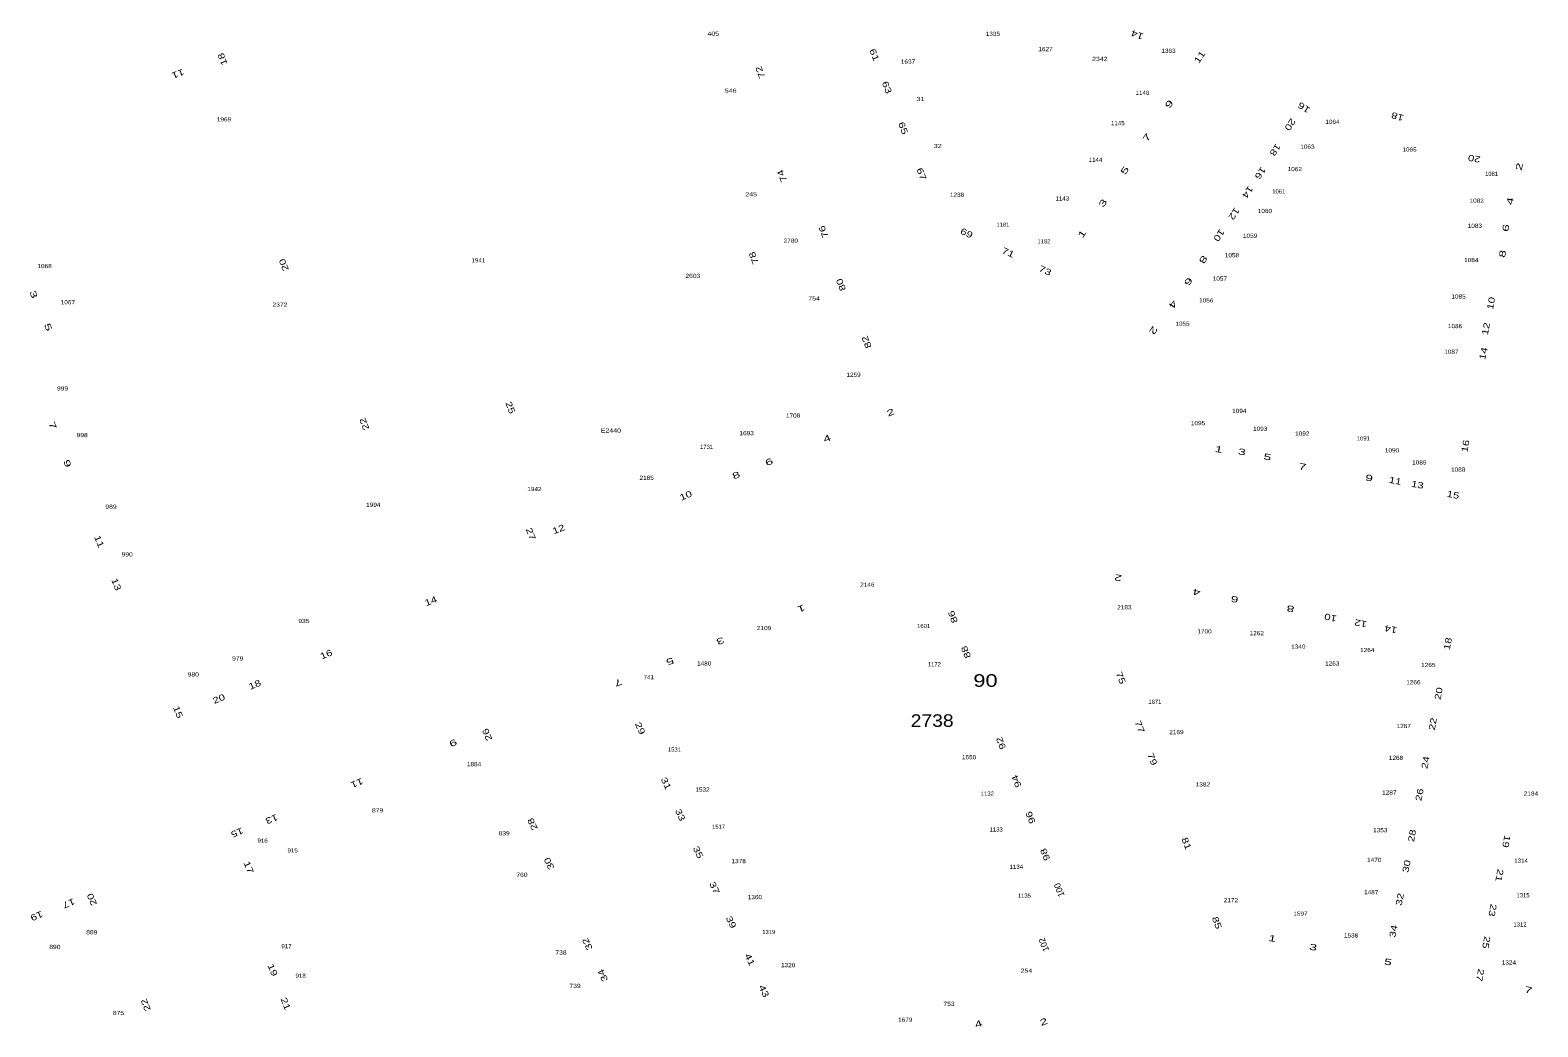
# Model space of a CAD drawing. Extents: x -828673 to -815583, y -1077737 to -1063807.
# Drawn here: x -821834.7 to -821473.8, y -1071578.1 to -1071339.7 of the extents above; entities that cross this region are included whole.
import ezdxf
from ezdxf.enums import TextEntityAlignment as Align

# ---------------------------------------------------------------- set-up
doc = ezdxf.new("R2010")
doc.units = 0
doc.header["$LTSCALE"] = 0.4
doc.layers.add('1', color=7, linetype='Continuous')
doc.layers.add('2', color=7, linetype='Continuous')

msp = doc.modelspace()

# ---------------------------------------------------------------- texts
at = {"layer": '1'}
for s, height, width, p in [('405', 1, 1.25, (-821671.188, -1071341.038)), ('1335', 1, 1.15, (-821604.281, -1071341.054)), ('1627', 1, 1.15, (-821591.685, -1071344.708)), ('1363', 1, 1.15, (-821562.25, -1071345.113)), ('1637', 1, 1.15, (-821624.588, -1071347.691)), ('2342', 1, 1.25, (-821578.668, -1071347.05)), ('546', 1, 1.25, (-821667.027, -1071354.653)), ('31', 1, 1.3, (-821621.598, -1071356.638)), ('1146', 1, 1.1, (-821568.474, -1071355.165)), ('1969', 1, 1.15, (-821788.3, -1071361.508)), ('1145', 1, 1.1, (-821574.374, -1071362.426)), ('1064', 1, 1.15, (-821522.997, -1071362.098)), ('32', 1, 1.3, (-821617.463, -1071367.889)), ('1144', 1, 1.1, (-821579.713, -1071371.186)), ('1063', 1, 1.15, (-821528.998, -1071368.038)), ('1065', 1, 1.15, (-821504.567, -1071368.736)), ('1062', 1, 1.15, (-821532.014, -1071373.407)), ('1081', 1, 1.05, (-821484.914, -1071374.549)), ('245', 1, 1.25, (-821662.136, -1071379.447)), ('1238', 1, 1.15, (-821612.847, -1071379.547)), ('1143', 1, 1.1, (-821587.656, -1071380.437)), ('1061', 1, 1.05, (-821535.851, -1071378.752)), ('1082', 1, 1.15, (-821488.47, -1071380.966)), ('1060', 1, 1.15, (-821539.184, -1071383.421)), ('1083', 1, 1.15, (-821488.92, -1071386.975)), ('2780', 1, 1.15, (-821652.642, -1071390.526)), ('1182', 1, 1.05, (-821592.057, -1071390.696)), ('1059', 1, 1.15, (-821542.709, -1071389.362)), ('1941', 1, 1.1, (-821727.402, -1071395.23)), ('1058', 1, 1.15, (-821547.052, -1071394.011)), ('1084', 1, 1.15, (-821489.778, -1071395.171)), ('1068', 1, 1.15, (-821831.238, -1071396.601)), ('2603', 1, 1.2, (-821676.094, -1071398.954)), ('1057', 1, 1.15, (-821549.942, -1071399.602)), ('1067', 1, 1.15, (-821825.68, -1071405.256)), ('2372', 1, 1.2, (-821774.924, -1071405.843)), ('754', 1, 1.25, (-821647.065, -1071404.341)), ('1056', 1, 1.15, (-821553.212, -1071404.811)), ('1085', 1, 1.15, (-821492.82, -1071403.88)), ('1055', 1, 1.15, (-821558.892, -1071410.391)), ('1086', 1, 1.15, (-821493.646, -1071410.964)), ('1087', 1, 1.15, (-821494.535, -1071417.095)), ('1259', 1, 1.15, (-821637.617, -1071422.609)), ('999', 1, 1.2, (-821826.937, -1071425.871)), ('1708', 1, 1.15, (-821652.095, -1071432.365)), ('1094', 1, 1.15, (-821545.293, -1071431.249)), ('E2440', 1, 1.25, (-821695.687, -1071435.934)), ('1095', 1, 1.15, (-821555.174, -1071434.17)), ('1093', 1, 1.15, (-821540.287, -1071435.527)), ('998', 1, 1.2, (-821822.249, -1071437.041)), ('1693', 1, 1.15, (-821663.208, -1071436.577)), ('1092', 1, 1.15, (-821530.223, -1071436.674)), ('1091', 1, 1.05, (-821515.61, -1071437.832)), ('1731', 1, 1.05, (-821672.802, -1071439.858)), ('1090', 1, 1.15, (-821508.752, -1071440.69)), ('1089', 1, 1.15, (-821502.211, -1071443.581)), ('1088', 1, 1.15, (-821492.909, -1071445.296)), ('1942', 1, 1.15, (-821714.001, -1071449.947)), ('2185', 1, 1.15, (-821687.145, -1071447.254)), ('989', 1, 1.2, (-821815.346, -1071454.17)), ('1994', 1, 1.15, (-821752.564, -1071453.718)), ('990', 1, 1.2, (-821811.48, -1071465.581)), ('2146', 1, 1.15, (-821634.337, -1071472.817)), ('2183', 1, 1.15, (-821572.807, -1071478.229)), ('935', 1, 1.2, (-821769.168, -1071481.521)), ('1601', 1, 1.05, (-821620.839, -1071482.708)), ('2109', 1, 1.15, (-821659.034, -1071483.204)), ('1700', 1, 1.15, (-821553.616, -1071483.989)), ('1262', 1, 1.15, (-821541.116, -1071484.413)), ('1340', 1, 1.15, (-821531.174, -1071487.639)), ('1264', 1, 1.15, (-821514.664, -1071488.45)), ('979', 1, 1.2, (-821785.02, -1071490.467)), ('1480', 1, 1.15, (-821673.374, -1071491.669)), ('1172', 1, 1.05, (-821618.276, -1071491.857)), ('1263', 1, 1.15, (-821523.051, -1071491.683)), ('1265', 1, 1.15, (-821500.052, -1071492.027)), ('980', 1, 1.2, (-821795.652, -1071494.286)), ('741', 1, 1.1, (-821686.628, -1071494.94)), ('1266', 1, 1.15, (-821503.633, -1071496.163)), ('1671', 1, 1.05, (-821565.501, -1071500.845)), ('2738', 3, 1.15, (-821618.809, -1071506.34)), ('2169', 1, 1.15, (-821560.335, -1071508.091)), ('1267', 1, 1.15, (-821505.926, -1071506.622)), ('1531', 1, 1.05, (-821680.487, -1071512.267)), ('1650', 1, 1.15, (-821609.978, -1071514.095)), ('1268', 1, 1.15, (-821507.791, -1071514.243)), ('1884', 1, 1.15, (-821728.459, -1071515.769)), ('1532', 1, 1.15, (-821673.773, -1071521.832)), ('1382', 1, 1.15, (-821554.004, -1071520.599)), ('1287', 1, 1.15, (-821509.381, -1071522.534)), ('1132', 1, 1.05, (-821605.604, -1071522.803)), ('2184', 1, 1.15, (-821475.507, -1071522.788)), ('879', 1, 1.2, (-821751.531, -1071526.805)), ('839', 1, 1.2, (-821721.257, -1071532.303)), ('1517', 1, 1.05, (-821669.929, -1071530.716)), ('1133', 1, 1.05, (-821603.483, -1071531.377)), ('1353', 1, 1.15, (-821511.557, -1071531.554)), ('916', 1, 1.1, (-821779.07, -1071534.047)), ('915', 1, 1.1, (-821771.874, -1071536.388)), ('1378', 1, 1.15, (-821665.121, -1071538.949)), ('1134', 1, 1.1, (-821598.667, -1071540.306)), ('1470', 1, 1.15, (-821512.995, -1071538.669)), ('1314', 1, 1.1, (-821477.853, -1071538.832)), ('760', 1, 1.2, (-821716.989, -1071542.218)), ('1360', 1, 1.15, (-821661.233, -1071547.569)), ('1135', 1, 1.05, (-821596.731, -1071547.208)), ('1487', 1, 1.15, (-821513.726, -1071546.387)), ('1315', 1, 1.05, (-821477.389, -1071547.114)), ('2172', 1, 1.15, (-821547.295, -1071548.296)), ('1597', 1, 1.15, (-821530.662, -1071551.523)), ('1312', 1, 1.05, (-821478.12, -1071554.117)), ('889', 1, 1.2, (-821819.955, -1071555.972)), ('1319', 1, 1.05, (-821657.92, -1071555.923)), ('1538', 1, 1.15, (-821518.545, -1071556.729)), ('890', 1, 1.2, (-821828.782, -1071559.472)), ('917', 1, 1.1, (-821773.337, -1071559.297)), ('738', 1, 1.2, (-821707.655, -1071560.822)), ('1320', 1, 1.15, (-821653.281, -1071563.835)), ('254', 1, 1.25, (-821596.245, -1071565.153)), ('1324', 1, 1.15, (-821480.773, -1071563.186)), ('918', 1, 1.1, (-821769.97, -1071566.365)), ('739', 1, 1.2, (-821704.288, -1071568.792)), ('753', 1, 1.2, (-821614.774, -1071573.09)), ('875', 1, 1.2, (-821813.558, -1071575.277)), ('1679', 1, 1.15, (-821625.244, -1071576.892))]:
    msp.add_text(s, height=height, dxfattribs=dict(at, width=width)).set_placement(p, align=Align.CENTER)
msp.add_text('1181', height=1, dxfattribs=at).set_placement((-821601.89, -1071386.714), align=Align.CENTER)
at = {"layer": '2'}
for s, rotation, width, p in [('14', 159.114, 1.35, (-821569.4446, -1071340.0971)), ('61', 291.704, 1.35, (-821633.3205, -1071345.8591)), ('11', 56.244, 1.35, (-821554.164, -1071346.5257)), ('18', 111.243, 1.35, (-821787.9617, -1071346.3587)), ('72', 110.651, 1.35, (-821659.245, -1071349.4935)), ('11', 201.198, 1.35, (-821799.5713, -1071349.4138)), ('63', 291.682, 1.35, (-821630.3252, -1071353.6339)), ('9', 56.376, 1.7, (-821561.4695, -1071357.7733)), ('16', 145.72, 1.35, (-821529.3961, -1071357.59)), ('18', 164.393, 1.35, (-821507.2332, -1071359.6363)), ('65', 291.656, 1.35, (-821626.4378, -1071363.3782)), ('20', 236.387, 1.35, (-821533.7374, -1071361.8428)), ('7', 55.91, 1.7, (-821566.8035, -1071365.7849)), ('18', 236.445, 1.35, (-821537.306, -1071367.8994)), ('20', 169.274, 1.35, (-821488.9204, -1071369.671)), ('74', 112.041, 1.35, (-821654.0668, -1071374.289)), ('67', 291.792, 1.35, (-821622.0454, -1071374.3511)), ('5', 56.192, 1.7, (-821572.0968, -1071373.6548)), ('16', 236.31, 1.35, (-821540.863, -1071373.4565)), ('2', 79.228, 1.65, (-821477.5619, -1071372.4752)), ('14', 236.564, 1.35, (-821543.9053, -1071378.0093)), ('3', 56.711, 1.7, (-821577.3325, -1071381.4506)), ('4', 79.404, 1.65, (-821479.7607, -1071380.7069)), ('12', 236.615, 1.35, (-821547.1741, -1071383.1868)), ('76', 112.012, 1.35, (-821644.1181, -1071387.6376)), ('69', 334.871, 1.35, (-821610.885, -1071388.9045)), ('1', 55.94, 1.7, (-821582.3339, -1071388.8315)), ('10', 236.487, 1.35, (-821550.7633, -1071388.3334)), ('6', 79.144, 1.65, (-821480.7755, -1071387.1233)), ('71', 336.026, 1.35, (-821600.9282, -1071393.5379)), ('20', 111.261, 1.35, (-821773.2853, -1071395.5725)), ('78', 111.758, 1.35, (-821660.8306, -1071393.893)), ('8', 236.284, 1.7, (-821554.551, -1071394.1472)), ('8', 79.38, 1.65, (-821481.5713, -1071393.3167)), ('73', 334.507, 1.35, (-821592.0783, -1071397.8476)), ('6', 236.361, 1.7, (-821558.1057, -1071399.3875)), ('3', 291.269, 1.65, (-821834.5554, -1071403.1584)), ('80', 111.577, 1.35, (-821639.9281, -1071400.3083)), ('4', 236.203, 1.7, (-821561.79, -1071404.8503)), ('10', 79.487, 1.35, (-821484.3106, -1071405.1478)), ('5', 291.833, 1.65, (-821831.0714, -1071410.9901)), ('12', 79.148, 1.35, (-821485.5478, -1071411.2472)), ('82', 111.754, 1.35, (-821633.8087, -1071414.0205)), ('2', 236.271, 1.7, (-821566.4542, -1071411.098)), ('14', 77.695, 1.35, (-821486.1682, -1071417.1873)), ('25', 291.27, 1.35, (-821720.4525, -1071430.2254)), ('2', 22.319, 1.65, (-821628.4963, -1071431.8078)), ('7', 292.215, 1.65, (-821830.0063, -1071434.5064)), ('22', 111.292, 1.35, (-821754.02, -1071433.6318)), ('4', 22.214, 1.65, (-821643.7005, -1071438.0233)), ('16', 79.54, 1.35, (-821490.4649, -1071439.2907)), ('6', 22.376, 1.65, (-821657.5555, -1071443.6539)), ('1', 348.939, 1.65, (-821550.3559, -1071440.6917)), ('3', 349.476, 1.65, (-821544.792, -1071441.2911)), ('5', 348.709, 1.65, (-821538.6898, -1071442.4975)), ('9', 291.791, 1.65, (-821826.4812, -1071443.5961)), ('8', 22.039, 1.65, (-821665.4359, -1071446.8412)), ('7', 349.124, 1.65, (-821530.3065, -1071444.8118)), ('9', 349.176, 1.65, (-821514.3613, -1071447.537)), ('11', 348.94, 1.35, (-821508.1189, -1071448.2086)), ('13', 349.519, 1.35, (-821502.7799, -1071449.1396)), ('10', 22.539, 1.35, (-821677.494, -1071451.7006)), ('15', 349.17, 1.35, (-821494.2704, -1071451.5567)), ('27', 291.23, 1.35, (-821715.5636, -1071460.4454)), ('12', 21, 1.35, (-821707.9703, -1071459.7462)), ('11', 291.943, 1.35, (-821818.8685, -1071462.2532)), ('13', 291.268, 1.35, (-821814.7665, -1071472.5115)), ('2', 169.38, 1.65, (-821574.1633, -1071469.9463)), ('4', 169.077, 1.65, (-821555.3999, -1071473.4094)), ('14', 21.559, 1.35, (-821738.5371, -1071476.9473)), ('1', 202.214, 1.65, (-821650.4085, -1071477.3276)), ('6', 170.004, 1.65, (-821546.2808, -1071475.0843)), ('8', 169.599, 1.65, (-821532.9111, -1071477.3759)), ('86', 110.69, 1.35, (-821613.1619, -1071479.749)), ('10', 167.914, 1.35, (-821523.2955, -1071479.4758)), ('12', 169.563, 1.35, (-821516.1071, -1071480.8516)), ('14', 169.001, 1.35, (-821508.8789, -1071482.2459)), ('3', 202.256, 1.65, (-821669.7864, -1071485.0984)), ('18', 79.38, 1.35, (-821494.6707, -1071486.5787)), ('16', 22.515, 1.35, (-821763.5492, -1071489.6804)), ('88', 111.589, 1.35, (-821610.0296, -1071488.192)), ('5', 201.617, 1.65, (-821681.8302, -1071489.9782)), ('18', 22.166, 1.35, (-821780.657, -1071496.937)), ('7', 202.156, 1.65, (-821694.2437, -1071495.0647)), ('75', 291.203, 1.35, (-821574.3371, -1071494.8863)), ('20', 22.274, 1.35, (-821789.2533, -1071500.3205)), ('20', 79.425, 1.35, (-821496.8619, -1071498.5066)), ('15', 291.791, 1.35, (-821799.9955, -1071503.0521)), ('26', 112.515, 1.35, (-821724.6316, -1071507.9182)), ('29', 295.504, 1.35, (-821689.3741, -1071507.0016)), ('77', 291.654, 1.35, (-821569.8309, -1071506.5643)), ('22', 79.563, 1.35, (-821498.2616, -1071505.7779)), ('9', 203.047, 1.65, (-821733.7564, -1071509.4927)), ('92', 111.239, 1.35, (-821601.6406, -1071509.9867)), ('79', 291.801, 1.35, (-821566.7982, -1071514.341)), ('24', 79.106, 1.35, (-821500.0067, -1071514.9932)), ('94', 111.366, 1.35, (-821597.9299, -1071519.0922)), ('11', 202.953, 1.35, (-821756.7655, -1071519.0967)), ('31', 295.364, 1.35, (-821683.1617, -1071520.1767)), ('26', 79.511, 1.35, (-821501.4421, -1071522.7005)), ('13', 202.562, 1.35, (-821777.1587, -1071527.7239)), ('28', 115.501, 1.35, (-821713.7948, -1071529.2924)), ('33', 294.664, 1.35, (-821679.7839, -1071527.6835)), ('96', 111.527, 1.35, (-821594.5739, -1071527.7567)), ('15', 202.568, 1.35, (-821785.4457, -1071530.9321)), ('28', 79.614, 1.35, (-821503.2318, -1071532.4982)), ('19', 259.313, 1.35, (-821482.1029, -1071533.6094)), ('35', 294.931, 1.35, (-821675.4974, -1071536.6559)), ('98', 111.586, 1.35, (-821591.0833, -1071536.5964)), ('81', 291.512, 1.35, (-821558.6264, -1071534.5115)), ('17', 292.756, 1.35, (-821783.0833, -1071540.2349)), ('30', 116.634, 1.35, (-821709.8274, -1071538.7112)), ('30', 79.219, 1.35, (-821504.5465, -1071539.8223)), ('37', 295.458, 1.35, (-821671.5704, -1071545.1536)), ('21', 259.34, 1.35, (-821483.7553, -1071541.7278)), ('20', 112.971, 1.35, (-821819.2312, -1071547.3557)), ('32', 78.69, 1.35, (-821506.1679, -1071547.7366)), ('19', 202.601, 1.35, (-821833.4133, -1071550.8868)), ('17', 203.24, 1.35, (-821825.7376, -1071547.8697)), ('23', 259.157, 1.35, (-821485.399, -1071550.0689)), ('39', 295.944, 1.35, (-821667.5914, -1071553.3759)), ('85', 290.968, 1.35, (-821551.353, -1071553.4581)), ('34', 79.61, 1.35, (-821507.6887, -1071555.3593)), ('32', 115.411, 1.35, (-821700.6757, -1071557.9783)), ('1', 349.241, 1.65, (-821537.5365, -1071557.6759)), ('25', 259.295, 1.35, (-821486.8975, -1071557.7627)), ('41', 295.5, 1.35, (-821663.1212, -1071562.3356)), ('3', 348.648, 1.65, (-821527.7596, -1071559.7714)), ('19', 292.908, 1.35, (-821777.3475, -1071564.7736)), ('34', 115.431, 1.35, (-821696.9782, -1071565.4746)), ('5', 348.781, 1.65, (-821509.8429, -1071563.3083)), ('27', 259.266, 1.35, (-821488.3612, -1071565.6023)), ('43', 294.864, 1.35, (-821659.744, -1071569.8417)), ('7', 348.285, 1.65, (-821476.2358, -1071570.0063)), ('22', 111.801, 1.35, (-821806.3468, -1071572.588)), ('21', 292.051, 1.35, (-821774.2257, -1071572.8404)), ('4', 21.958, 1.65, (-821607.4674, -1071578.0944)), ('2', 20.768, 1.65, (-821591.8519, -1071577.5912))]:
    msp.add_text(s, height=1.5, rotation=rotation, dxfattribs=dict(at, width=width)).set_placement(p, align=Align.CENTER)
at = {"layer": '2', "width": 1.3}
msp.add_text('90', height=3, dxfattribs=at).set_placement((-821606.049, -1071496.75), align=Align.CENTER)
at = {"layer": '2'}
for s, rotation, p in [('100', 111.689, (-821587.7187, -1071545.0862)), ('102', 111.877, (-821591.3848, -1071558.1685))]:
    msp.add_text(s, height=1.5, rotation=rotation, dxfattribs=at).set_placement(p, align=Align.CENTER)

doc.saveas('drawing.dxf')
